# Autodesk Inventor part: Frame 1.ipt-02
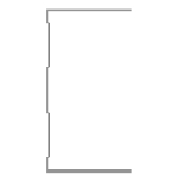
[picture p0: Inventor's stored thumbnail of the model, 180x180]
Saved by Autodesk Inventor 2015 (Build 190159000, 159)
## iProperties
IsCustomPart: 1
Created: 2015-04
Part Number: Frame 1.ipt-02
Material: Aluminum 6061
Description: Kévin Novo
Document SubType Name: Modeling
Standard: Kevin
Designer: suporte
Standards Organization: Kevin
Language: en-US
Size Designation: (Unnamed 2)
Categories: <MemberInstance><Categories><Category DisplayName="Structural Shapes" InternalName="089c4875-fa83-4c05-b084-43b9cc11f5ed" Mnemonic="GRDR"><CategoryParameter Dis
Density: 2.7 g/cm^3
Appearance: Aluminum - Flat
_CCFamilyMember: 2
_CCFamilyDisplayName: Kévin - Kévin Novo
_FrameMemberDoc: Frame Member File
_Version: 15.0.0
_GetPNFromCC: 1
G_W: 50,000 mm
G_H: 75,000 mm
G_L: 2100,000 mm
+C3D10A1A-A597-4B71-987A-FDA6CC0638FB+CUTDETAIL1: Notch
+61D623B8-6D8C-462B-A5EA-D63A214E0D71+CUTDETAIL2: Notch
Author: suporte
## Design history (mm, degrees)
node "Start Plane"
node "End Plane"
sketch "Sketch"
  geometry: L1 (24.7, 37.5)-(24.7, 36.9); L2 (24.7, 36.9)-(-24.7, 36.9); L3 (-24.7, -36.9)-(24.7, -36.9); L4 (24.7, -36.9)-(24.7, -37.5); L5 (24.7, -37.5)-(-25.3, -37.5); L6 (-25.3, 37.5)-(24.7, 37.5); L7 (-24.7, 36.9)-(-24.7, 31.9); L8 (-24.7, 31.9)-(-23.3, 30.5); L9 (-23.3, 30.5)-(-23.3, 10.934); L10 (-23.3, 10.934)-(-24.7, 9.534); L11 (-24.7, 9.534)-(-24.7, -9.534); L12 (-24.7, -9.534)-(-23.3, -10.934); L13 (-23.3, -10.934)-(-23.3, -30.5); L14 (-23.3, -30.5)-(-24.7, -31.9); L15 (-24.7, -31.9)-(-24.7, -36.9); L16 (-25.3, -37.5)-(-25.3, -31.651); L17 (-25.3, -31.651)-(-23.9, -30.251); L18 (-23.9, -30.251)-(-23.9, -11.183); L19 (-23.9, -11.183)-(-25.3, -9.783); L20 (-25.3, -9.783)-(-25.3, 9.783); L21 (-25.3, 9.783)-(-23.9, 11.183); L22 (-23.9, 11.183)-(-23.9, 30.251); L23 (-23.9, 30.251)-(-25.3, 31.651); L24 (-25.3, 31.651)-(-25.3, 37.5); L25 (-25.3, 0)-(30.37, 0); 3 further points
  constraints: 50 end point, 10 point on line, 9 parallel, 5 perpendicular, 4 equal length, 3 midpoint, 3 vertical, 2 vertical alignment, 1 collinear, 1 horizontal, 1 horizontal alignment
  dimensions: "d3" = 0.6 distance of L1.start L1.end (= d6); "d5" = 75 distance between parallel lines of L5 L6; "d6" = 0.6 distance between parallel lines of L24 L7 (= d8); "d7" = 0.6 distance between parallel lines of L8 L23 (= d8); "d8" = 0.6 distance between parallel lines of L22 L9 (= d12); "Espessura" = 0.6 distance between parallel lines of L17 L14; "d10" = 0.6 distance between parallel lines of L13 L18 (= Espessura); "d11" = 0.6 distance between parallel lines of L12 L19 (= Espessura); "d12" = 0.6 distance between parallel lines of L21 L10 (= d11); "d13" = 5 distance of L2.end L7.end; "d15" = 135 deg angle of L9 L8; "d16" = 2 distance between parallel lines of L24 L9; "d17" = 50 distance of L6.start L1.start
extrude "Body" join sketch "Sketch" stored distance "d24" = 0.13; taper "d25" = 0 deg
node "Driven Length"
  sketch "Sketch10"
    geometry: L1 (0, 0)-(10, 0) reference
    constraints: 2 end point, 1 horizontal
  workplane "Work Plane7"
  sketch "Sketch11"
    geometry: L1 (-2, 0)-(12, 0) reference; L2 (-2, 2100)-(12, 2100) reference
    dimensions: "d27" = 2100 distance between parallel lines of L1 L2 (derived)
workplane "Work Plane8"
workplane "Work Plane9"
workplane "Work Plane10"
sketch "Sketch12"
  geometry: L1 (24.7, 37.5)-(24.7, 36.9); L2 (24.7, 36.9)-(-24.7, 36.9); L3 (-24.7, 36.9)-(-24.7, 31.9); L4 (-24.7, 31.9)-(-23.3, 30.5); L5 (-23.3, 30.5)-(-23.3, 10.934); L6 (-23.3, 10.934)-(-24.7, 9.534); L7 (-24.7, 9.534)-(-24.7, -9.534); L8 (-24.7, -9.534)-(-23.3, -10.934); L9 (-23.3, -10.934)-(-23.3, -30.5); L10 (-23.3, -30.5)-(-24.7, -31.9); L11 (-24.7, -31.9)-(-24.7, -36.9); L12 (-24.7, -36.9)-(24.7, -36.9); L13 (24.7, -36.9)-(24.7, -37.5); L14 (24.7, -37.5)-(-25.3, -37.5); L15 (-25.3, -37.5)-(-25.3, -31.651); L16 (-25.3, -31.651)-(-23.9, -30.251); L17 (-23.9, -30.251)-(-23.9, -11.183); L18 (-23.9, -11.183)-(-25.3, -9.783); L19 (-25.3, -9.783)-(-25.3, 9.783); L20 (-25.3, 9.783)-(-23.9, 11.183); L21 (-23.9, 11.183)-(-23.9, 30.251); L22 (-23.9, 30.251)-(-25.3, 31.651); L23 (-25.3, 31.651)-(-25.3, 37.5); L24 (-25.3, 37.5)-(24.7, 37.5)
  constraints: 48 end point, 10 point on line
extrude "Extrusion3" cut sketch "Sketch12" stored distance "d36" = 0.13; taper "d37" = 0 deg
workplane "Work Plane11"
workplane "Work Plane12"
workplane "Work Plane13"
sketch "Sketch13"
  geometry: L1 (24.7, 37.5)-(24.7, 36.9); L2 (24.7, 36.9)-(-24.7, 36.9); L3 (-24.7, 36.9)-(-24.7, 31.9); L4 (-24.7, 31.9)-(-23.3, 30.5); L5 (-23.3, 30.5)-(-23.3, 10.934); L6 (-23.3, 10.934)-(-24.7, 9.534); L7 (-24.7, 9.534)-(-24.7, -9.534); L8 (-24.7, -9.534)-(-23.3, -10.934); L9 (-23.3, -10.934)-(-23.3, -30.5); L10 (-23.3, -30.5)-(-24.7, -31.9); L11 (-24.7, -31.9)-(-24.7, -36.9); L12 (-24.7, -36.9)-(24.7, -36.9); L13 (24.7, -36.9)-(24.7, -37.5); L14 (24.7, -37.5)-(-25.3, -37.5); L15 (-25.3, -37.5)-(-25.3, -31.651); L16 (-25.3, -31.651)-(-23.9, -30.251); L17 (-23.9, -30.251)-(-23.9, -11.183); L18 (-23.9, -11.183)-(-25.3, -9.783); L19 (-25.3, -9.783)-(-25.3, 9.783); L20 (-25.3, 9.783)-(-23.9, 11.183); L21 (-23.9, 11.183)-(-23.9, 30.251); L22 (-23.9, 30.251)-(-25.3, 31.651); L23 (-25.3, 31.651)-(-25.3, 37.5); L24 (-25.3, 37.5)-(24.7, 37.5)
  constraints: 48 end point, 10 point on line
extrude "Extrusion4" cut sketch "Sketch13" stored distance "d38" = 0.13; taper "d39" = 0 deg
body "Solid1"
other parameters: "G_OFFSET_START" = 0 [user parameter; used in 1 equation term], "G_OFFSET_END" = 0 [user parameter; used in 1 equation term], "d22" = 0 (computed from G_OFFSET_START), "G_L" = 2100 (= d27) [user parameter], "d34" = 90 deg
